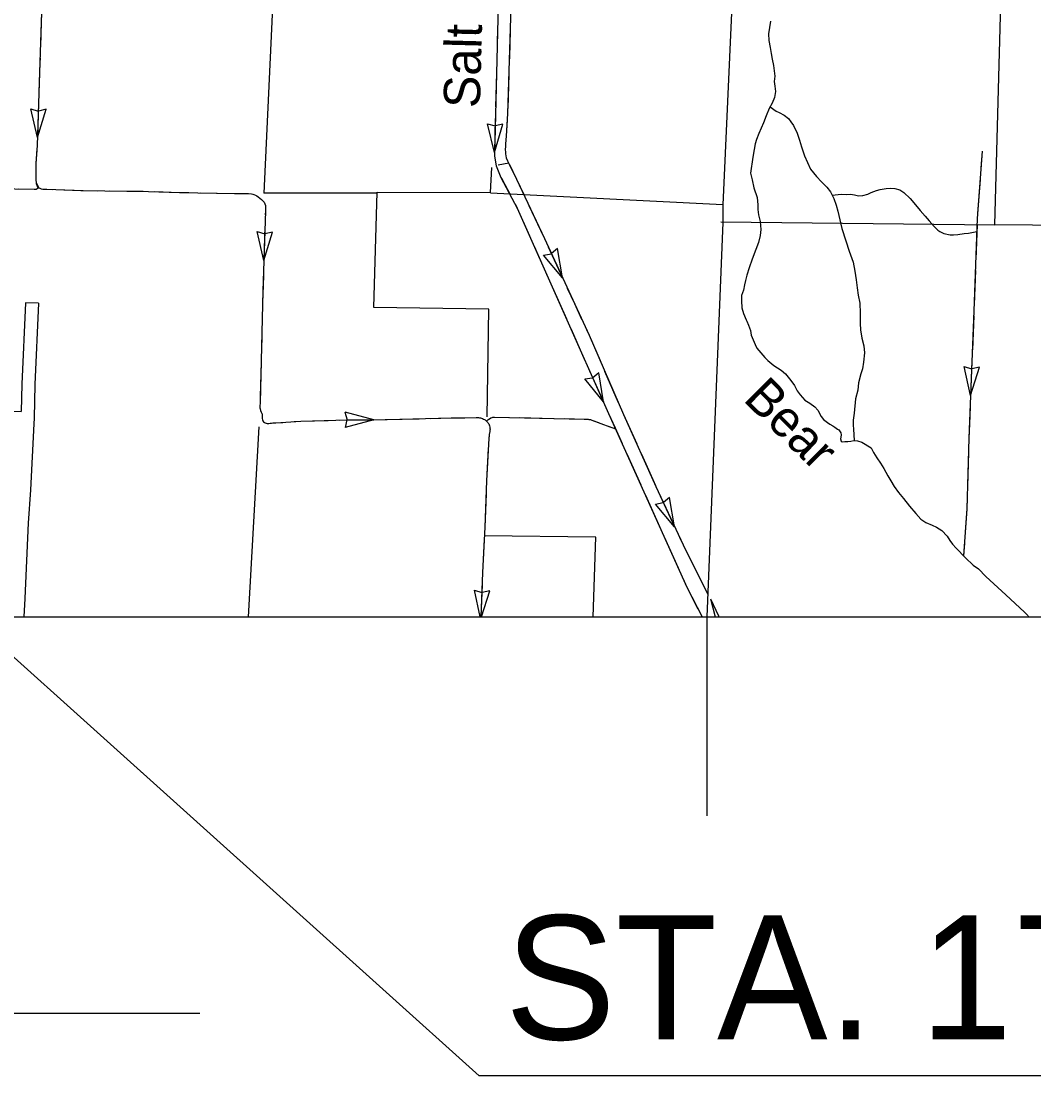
# Model space of a CAD drawing. Extents: x 1196286 to 1268366, y 2040822 to 2082115.
# Drawn here: x 1222892 to 1227299, y 2045968 to 2050559 of the extents above; entities that cross this region are included whole.
import ezdxf

# ---------------------------------------------------------------- set-up
doc = ezdxf.new("R2010")
doc.units = 0
for name, color, linetype in [('55', 7, 'Continuous'), ('60', 7, 'Continuous'), ('62', 7, 'Continuous'), ('63', 7, 'Continuous'), ('Level 70', 7, 'Continuous'), ('Level 72', 7, 'Continuous'), ('Level 8', 7, 'Continuous')]:
    doc.layers.add(name, color=color, linetype=linetype)

msp = doc.modelspace()

# ---------------------------------------------------------------- linework, layer by layer
at = {"layer": '55'}
msp.add_lwpolyline([(1226105.9, 2053795.1), (1226044.2, 2051971.2), (1226037.7, 2051807.6), (1226034.2, 2051719.9), (1225946, 2049758.8), (1225945.2, 2049681.6), (1225876.1, 2047966.3)], dxfattribs=at)
at = {"layer": '60'}
for points in [[(1223991.5, 2050744), (1223948.5, 2049810.4)], [(1224441.9, 2049810), (1223948.5, 2049810.4)], [(1225946, 2049758.8), (1224935.1, 2049809.8)], [(1225937.1, 2049684.5), (1227129.1, 2049672.5)], [(1223927.2, 2048792.6), (1223880.6, 2047966.3)]]:
    msp.add_lwpolyline(points, dxfattribs=at)
at = {"layer": '62'}
for points in [[(1226152.8, 2050559.2), (1226144.9, 2050503.4), (1226146.3, 2050474.4), (1226151.1, 2050444.3), (1226155.9, 2050417.9), (1226161.1, 2050393.1), (1226166.7, 2050365.2), (1226169.4, 2050343), (1226171.6, 2050319.7), (1226168.6, 2050296.4), (1226172.8, 2050276.1), (1226174.3, 2050252.4), (1226170.5, 2050226.1), (1226161.2, 2050202.2), (1226147.3, 2050178.4), (1226134.1, 2050147.1), (1226123.5, 2050116.4), (1226111.9, 2050093.3), (1226101.8, 2050069.1), (1226092.4, 2050043.3), (1226086.5, 2050025.3), (1226082, 2049999.5), (1226076.3, 2049966.5), (1226066.9, 2049896.8), (1226072.9, 2049868.2), (1226081.3, 2049833.1), (1226094.5, 2049790.4), (1226098.5, 2049759.2), (1226098.2, 2049738.2), (1226101.2, 2049715.9), (1226107.9, 2049686.2), (1226111.1, 2049651.2), (1226108.1, 2049625.7), (1226100.5, 2049594.6), (1226089.2, 2049565.1), (1226073.5, 2049522.9), (1226060.6, 2049484.4), (1226049.6, 2049452.7), (1226044.4, 2049429.4), (1226040.7, 2049411.5), (1226035.1, 2049388.3), (1226027.6, 2049364.3), (1226026.5, 2049341.4), (1226029, 2049310.2), (1226035.8, 2049285.7), (1226047.7, 2049258.1), (1226050.3, 2049253.5), (1226058.2, 2049236.1), (1226065.7, 2049212.4), (1226069.5, 2049191.3), (1226086.5, 2049150.8), (1226093.8, 2049135.7), (1226111, 2049114.7), (1226129.1, 2049094.9), (1226141.3, 2049082.3), (1226167.9, 2049060.5), (1226199.4, 2049039.4), (1226218.6, 2049023.3), (1226242.2, 2048994), (1226257.6, 2048972.7), (1226269.9, 2048949.2), (1226281.7, 2048932.1), (1226302.6, 2048908.5), (1226323.8, 2048896.2), (1226346, 2048880.4), (1226358.9, 2048865.6), (1226373.8, 2048837.9), (1226384.5, 2048825), (1226401.9, 2048812.3), (1226411.5, 2048804.6), (1226424.5, 2048797.3), (1226432.7, 2048791.9), (1226444.9, 2048783.1), (1226450.1, 2048780.4), (1226454.2, 2048776.2), (1226460, 2048767.1), (1226461, 2048758.4), (1226459.7, 2048747.5), (1226457.4, 2048740.8), (1226460.2, 2048730.3), (1226464.7, 2048727.6), (1226477.4, 2048728.9), (1226489.4, 2048729), (1226502.9, 2048731.1), (1226515.7, 2048733.9)], [(1226151.9, 2050186.2), (1226177.9, 2050167.4), (1226190.9, 2050160.8), (1226212.1, 2050148.9), (1226230.9, 2050135), (1226241.6, 2050121), (1226253.7, 2050105), (1226270, 2050071.3), (1226280.1, 2050041.1), (1226287.8, 2050011.7), (1226301.5, 2049972), (1226327.9, 2049914.1), (1226353.3, 2049881.8), (1226375.8, 2049859.7), (1226398.6, 2049835.7), (1226414.4, 2049815.5), (1226428.6, 2049786.3), (1226439.7, 2049757.6), (1226446.1, 2049732), (1226464, 2049655.8), (1226481.2, 2049603), (1226495.4, 2049557.3), (1226512.3, 2049509.7), (1226520.3, 2049470.5), (1226525.7, 2049432.1), (1226530.4, 2049397.8), (1226534.1, 2049365.5), (1226541.4, 2049331.9), (1226543.7, 2049287.9), (1226542.7, 2049243.2), (1226545.2, 2049215.4), (1226551, 2049179.3), (1226558.7, 2049144.9), (1226561.6, 2049114.5), (1226558.4, 2049074.3), (1226553.1, 2049045.5), (1226545.6, 2049023.4), (1226535.7, 2048984.9), (1226532.9, 2048952.6), (1226523.3, 2048914.5), (1226517.9, 2048852.2), (1226513.3, 2048822.6), (1226513.3, 2048800.4), (1226515, 2048783.5), (1226517.3, 2048733.8)], [(1226421.5, 2049801), (1226460.3, 2049805), (1226482.4, 2049803.9), (1226501.9, 2049805.1), (1226518.3, 2049802.2), (1226536.6, 2049798.2), (1226554.6, 2049799.8), (1226577.2, 2049805.4), (1226591.2, 2049812.7), (1226613.8, 2049821), (1226630.3, 2049826), (1226655.9, 2049830.1), (1226675, 2049832.1), (1226694.4, 2049830.3), (1226715.3, 2049824), (1226733.9, 2049812.8), (1226761.2, 2049786.4), (1226784.7, 2049759), (1226805, 2049735), (1226825.9, 2049710.3), (1226844, 2049689), (1226865.3, 2049664.2), (1226881.9, 2049648.9), (1226890.8, 2049642.4), (1226907.5, 2049634.3), (1226935.5, 2049628.2), (1226949, 2049628.7), (1226967.8, 2049629.9), (1226995.9, 2049634), (1227014.7, 2049636.3), (1227051.1, 2049643.6)], [(1226515.7, 2048733.9), (1226531.4, 2048732.5), (1226550.8, 2048726.2), (1226592, 2048702.3), (1226601.4, 2048681.8), (1226616, 2048658.3), (1226631.4, 2048634.8), (1226646.8, 2048611.6), (1226664.3, 2048579.8), (1226676.3, 2048557.5), (1226691.6, 2048533.6), (1226710.7, 2048507.7), (1226731.3, 2048481.5), (1226758.1, 2048447.6), (1226785.3, 2048415.3), (1226807.8, 2048391.6), (1226829.7, 2048376.6), (1226856.8, 2048364.6), (1226875.4, 2048356.4), (1226898.4, 2048342.1), (1226922, 2048317), (1226933.7, 2048298.4), (1226945.5, 2048282.4), (1226960.9, 2048264.5), (1227001.5, 2048222.9), (1227034.7, 2048191.6), (1227057.7, 2048175.1), (1227090.1, 2048141.9), (1227177.7, 2048061.7), (1227258.1, 2047986.8), (1227272.5, 2047971.9), (1227276.1, 2047966.3)], [(1225892, 2048044.5), (1225912.3, 2047966.3)], [(1225892, 2048044.5), (1225926.3, 2047970.7), (1225928.5, 2047966.3)]]:
    msp.add_lwpolyline(points, dxfattribs=at)
at = {"layer": '63'}
for p, q in [((1222963.6, 2050051.9), (1222934.4, 2050177.2)), ((1222934.4, 2050177.2), (1222967.2, 2050167.3)), ((1222963.6, 2050051.9), (1223001, 2050175)), ((1223001, 2050175), (1222967.6, 2050167.3)), ((1224952.2, 2049987.2), (1224921.9, 2050112.2)), ((1224921.9, 2050112.2), (1224954.8, 2050102.6)), ((1224952.2, 2049987.2), (1224988.5, 2050110.6)), ((1224988.5, 2050110.6), (1224955.2, 2050102.6)), ((1225014, 2049940.7), (1224968.7, 2049931.6)), ((1223948.8, 2049517.6), (1223919.4, 2049642.9)), ((1223919.4, 2049642.9), (1223952.2, 2049633)), ((1223948.8, 2049517.6), (1223986, 2049640.8)), ((1223986, 2049640.8), (1223952.6, 2049633)), ((1225166.1, 2049540.7), (1225199.9, 2049546.5)), ((1225248.4, 2049441.7), (1225166.1, 2049540.7)), ((1225226.7, 2049568.6), (1225200.3, 2049546.7)), ((1225248.4, 2049441.7), (1225226.7, 2049568.6)), ((1225406.4, 2049028.4), (1225379.8, 2049006.8)), ((1225426.5, 2048901.2), (1225406.4, 2049028.4)), ((1227024, 2048929.7), (1226995.7, 2049055.3)), ((1226995.7, 2049055.3), (1227028.4, 2049045.1)), ((1227024, 2048929.7), (1227062.3, 2049052.6)), ((1227062.3, 2049052.6), (1227028.9, 2049045.1)), ((1225345.5, 2049001.3), (1225379.4, 2049006.6)), ((1225426.5, 2048901.2), (1225345.5, 2049001.3)), ((1224301.4, 2048856.6), (1224311.3, 2048823.8)), ((1224426.8, 2048823.8), (1224302.4, 2048856.9)), ((1224426.8, 2048823.8), (1224302.5, 2048790.3)), ((1224303.5, 2048790), (1224311.3, 2048823.4)), ((1225713.6, 2048485.2), (1225687.3, 2048463.2)), ((1225735.9, 2048358.4), (1225713.6, 2048485.2)), ((1225653.2, 2048457), (1225686.9, 2048463)), ((1225735.9, 2048358.4), (1225653.2, 2048457)), ((1224890.5, 2047966.3), (1224864.8, 2048082.6)), ((1224864.8, 2048082.6), (1224897.5, 2048072.3)), ((1224895.5, 2047966.3), (1224931.4, 2048079.7)), ((1224931.4, 2048079.7), (1224897.9, 2048072.3))]:
    msp.add_line(p, q, dxfattribs=at)
for points in [[(1224978.1, 2051051.1), (1224951.7, 2049970.3), (1224960.1, 2049929.6), (1224980.1, 2049878.3), (1225051, 2049744.6), (1225448.7, 2048851.4), (1225789, 2048095.3), (1225855.5, 2047966.3)], [(1225029.5, 2050806.5), (1225009.5, 2050156.7), (1225003, 2050058.6), (1225000.4, 2050024.1), (1224999.6, 2050013.8), (1224999, 2049998.3), (1224999.4, 2049989.8), (1225000, 2049980.7), (1225001.2, 2049972.9), (1225003.5, 2049963.7), (1225008.7, 2049950.8), (1225016.1, 2049936.7), (1225048.3, 2049870.6), (1225169.4, 2049613.3), (1225363.6, 2049191.3), (1225513.1, 2048847.3), (1225654.1, 2048534), (1225772.6, 2048279.5), (1225880, 2048063.8)], [(1222983.9, 2050670.3), (1222979.9, 2050553.7), (1222974, 2050379.2), (1222968.5, 2050200), (1222962.5, 2050017.5), (1222957, 2049938.5), (1222956.5, 2049898.9), (1222956.6, 2049878), (1222956.8, 2049865.9), (1222957.3, 2049856.8), (1222957.8, 2049852.1), (1222958.8, 2049847.3), (1222961.1, 2049842.2), (1222963, 2049838.7), (1222964.3, 2049837), (1222966, 2049835.3), (1222967.3, 2049834.3)], [(1222981.4, 2050596.1), (1222979.9, 2050553.7), (1222976.3, 2050447.7)], [(1224965.4, 2050531.5), (1224961.8, 2050383)], [(1225020.8, 2050524.7), (1225018.5, 2050450.4)], [(1225018.5, 2050450.4), (1225016.2, 2050376.2)], [(1222974.6, 2050398.2), (1222974, 2050379.2), (1222970, 2050249.8)], [(1224960.6, 2050333.6), (1224957, 2050185.1)], [(1225014.7, 2050326.8), (1225010.1, 2050178.3)], [(1222968.5, 2050200.3), (1222968.5, 2050200), (1222963.6, 2050051.9)], [(1224955.8, 2050135.6), (1224952.2, 2049987.2)], [(1225007.6, 2050128.9), (1225003, 2050058.6), (1225000.4, 2050024.1), (1224999.6, 2050013.8), (1224999, 2049998.3), (1224999.4, 2049989.8), (1225000, 2049980.7), (1225000, 2049980.7)], [(1222961.4, 2050002.4), (1222957, 2049938.5), (1222956.9, 2049928.3)], [(1227074.5, 2049992.7), (1227053.1, 2049700), (1227038.7, 2049297.5), (1227016.6, 2048743.7), (1227007.4, 2048436.2), (1226993, 2048231.7)], [(1227074.5, 2049992.7), (1227053.1, 2049700), (1227038.7, 2049297.5), (1227016.6, 2048743.7), (1227007.4, 2048436.2), (1226993, 2048231.7)], [(1227074.5, 2049992.7), (1227069.1, 2049918.6)], [(1222956.9, 2049928.3), (1222956.5, 2049898.9), (1222956.6, 2049878), (1222956.8, 2049865.9), (1222957.3, 2049856.8), (1222969.2, 2049833)], [(1224958.3, 2049938.3), (1224960.1, 2049929.6), (1224980.1, 2049878.3), (1224984.9, 2049869.2)], [(1225017.1, 2049934.6), (1225048.3, 2049870.6), (1225081.2, 2049800.7)], [(1224984.9, 2049869.2), (1225019.7, 2049803.6)], [(1227065.5, 2049869.2), (1227054.7, 2049721.1)], [(1221967.6, 2049848.8), (1222178.4, 2049845.5), (1222865, 2049829.2), (1222949.7, 2049827), (1222955.3, 2049827.3), (1222958.6, 2049828), (1222962, 2049829.8), (1222967.3, 2049834.3)], [(1222883.1, 2049828.7), (1222949.7, 2049827), (1222955.3, 2049827.3), (1222958.6, 2049828), (1222962, 2049829.8), (1222967.3, 2049834.3), (1222969.2, 2049833), (1222973.8, 2049831.2), (1222980.2, 2049829.1), (1222987.2, 2049827.8), (1222992.9, 2049827.3), (1222999.2, 2049826.7), (1223003.9, 2049826.7), (1223028.1, 2049825.9)], [(1222967.3, 2049834.3), (1222969.2, 2049833), (1222973.8, 2049831.2), (1222980.2, 2049829.1), (1222987.2, 2049827.8), (1222992.9, 2049827.3), (1222999.2, 2049826.7), (1223003.9, 2049826.7), (1223162.3, 2049821.7), (1223446.9, 2049817.8), (1223581.8, 2049812.9), (1223822.7, 2049808.6), (1223881.1, 2049807.8), (1223894.8, 2049806.5), (1223901.1, 2049805.4), (1223905.6, 2049804), (1223911.7, 2049801.2), (1223917.5, 2049798.3), (1223924.5, 2049793.8), (1223931.1, 2049788.7), (1223938.5, 2049782), (1223943.9, 2049776.8), (1223949.3, 2049770.2), (1223953, 2049763.1), (1223955.2, 2049756.6), (1223956, 2049751.3), (1223956.1, 2049745.7), (1223955.5, 2049732.2), (1223944.8, 2049385.1), (1223932, 2048898.4), (1223931.3, 2048880.9), (1223931.2, 2048876.3), (1223932.1, 2048870.8), (1223934.5, 2048863.6), (1223937.1, 2048857.4), (1223939.9, 2048851.6), (1223940.7, 2048849), (1223941, 2048845.7), (1223941, 2048841.2), (1223941, 2048837), (1223941.2, 2048829.6), (1223942.1, 2048823.7), (1223944, 2048818.9), (1223947.2, 2048814.9), (1223951.1, 2048812), (1223954.5, 2048810), (1223958.9, 2048808.7), (1223963.1, 2048808), (1223966.3, 2048807.9), (1223970.9, 2048808.1), (1223976, 2048808.6), (1223982.5, 2048809.2), (1223987.8, 2048809.7), (1224001, 2048810.7), (1224109.4, 2048817.4), (1224312.3, 2048823.6), (1224423.3, 2048823.8), (1224485.9, 2048824.5), (1224763.7, 2048831.8), (1224876.5, 2048833.3), (1224883.1, 2048832.9), (1224887.4, 2048832.5), (1224890.9, 2048831.8), (1224895.2, 2048830.8), (1224900.5, 2048828.9), (1224904.8, 2048827), (1224908.1, 2048825.4), (1224911, 2048823.5), (1224914.1, 2048821), (1224917.6, 2048817.7)], [(1223077.6, 2049824.4), (1223151.8, 2049822)], [(1223151.8, 2049822), (1223162.3, 2049821.7), (1223226, 2049820.8)], [(1223275.5, 2049820.2), (1223424, 2049818.1)], [(1223473.5, 2049816.8), (1223581.8, 2049812.9), (1223621.9, 2049812.2)], [(1223671.4, 2049811.3), (1223819.9, 2049808.6)], [(1223869.4, 2049807.9), (1223881.1, 2049807.8), (1223894.8, 2049806.5), (1223901.1, 2049805.4), (1223905.6, 2049804), (1223911.7, 2049801.2), (1223917.5, 2049798.3), (1223924.5, 2049793.8), (1223931.1, 2049788.7), (1223938.5, 2049782), (1223943.9, 2049776.8), (1223949.3, 2049770.2), (1223953, 2049763.1), (1223955.2, 2049756.6), (1223956, 2049751.3), (1223956.1, 2049745.7), (1223955.5, 2049732.2), (1223955, 2049715.5)], [(1225042.9, 2049759.9), (1225051, 2049744.6), (1225104.4, 2049624.8)], [(1225102.3, 2049755.9), (1225165.5, 2049621.6)], [(1227052.1, 2049671.7), (1227046.8, 2049523.3)], [(1223953.4, 2049666), (1223948.8, 2049517.6)], [(1225124.5, 2049579.6), (1225184.9, 2049443.9)], [(1225186.3, 2049576.6), (1225248.4, 2049441.7)], [(1223947.3, 2049468.1), (1223945, 2049393.9)], [(1227045, 2049473.8), (1227039.7, 2049325.4)], [(1223945, 2049393.9), (1223944.8, 2049385.1), (1223943, 2049319.7)], [(1225205.1, 2049398.7), (1225265.4, 2049263)], [(1225269.1, 2049396.8), (1225300.1, 2049329.3)], [(1225300.1, 2049329.3), (1225331.2, 2049261.9)], [(1223941.7, 2049270.2), (1223937.9, 2049121.7)], [(1227037.8, 2049276), (1227031.9, 2049127.6)], [(1225285.6, 2049217.8), (1225346, 2049082.1)], [(1225351.9, 2049216.9), (1225363.6, 2049191.3), (1225411.6, 2049081)], [(1223936.6, 2049072.3), (1223932.7, 2048923.8)], [(1227029.9, 2049078.1), (1227024, 2048929.7)], [(1225366.1, 2049036.9), (1225426.5, 2048901.2)], [(1225431.3, 2049035.6), (1225490.5, 2048899.4)], [(1223931.6, 2048874.4), (1223932.1, 2048870.8), (1223934.5, 2048863.6), (1223937.1, 2048857.4), (1223939.9, 2048851.6), (1223940.7, 2048849), (1223941, 2048845.7), (1223941, 2048841.2), (1223941, 2048837), (1223941.2, 2048829.6), (1223942.1, 2048823.7), (1223944, 2048818.9), (1223947.2, 2048814.9), (1223951.1, 2048812), (1223954.5, 2048810), (1223958.9, 2048808.7), (1223963.1, 2048808), (1223966.3, 2048807.9), (1223970.9, 2048808.1), (1223976, 2048808.6), (1223982.5, 2048809.2), (1223987.8, 2048809.7), (1224001, 2048810.7), (1224031, 2048812.5)], [(1225446.6, 2048856), (1225448.7, 2048851.4), (1225477.1, 2048788.3)], [(1225510.3, 2048854), (1225513.1, 2048847.3), (1225571.1, 2048718.5)], [(1227022.1, 2048880.3), (1227019.1, 2048806.1)], [(1224080.4, 2048815.6), (1224109.4, 2048817.4), (1224228.8, 2048821)], [(1224278.3, 2048822.6), (1224312.3, 2048823.6), (1224423.3, 2048823.8), (1224426.8, 2048823.8)], [(1224476.3, 2048824.4), (1224485.9, 2048824.5), (1224550.5, 2048826.2)], [(1224550.5, 2048826.2), (1224624.7, 2048828.1)], [(1224674.2, 2048829.4), (1224763.7, 2048831.8), (1224822.7, 2048832.6)], [(1224872.2, 2048833.3), (1224876.5, 2048833.3), (1224883.1, 2048832.9), (1224887.4, 2048832.5), (1224890.9, 2048831.8), (1224895.2, 2048830.8), (1224900.5, 2048828.9), (1224904.8, 2048827), (1224908.1, 2048825.4), (1224911, 2048823.5), (1224914.1, 2048821), (1224917.6, 2048817.7), (1224923.7, 2048823), (1224927.5, 2048826), (1224930.5, 2048828), (1224936.2, 2048831.5), (1224942.2, 2048834.3), (1224945.3, 2048835.2), (1224947.7, 2048835.6), (1224952.2, 2048835.6), (1225011.1, 2048834.3)], [(1224917.6, 2048817.7), (1224920.5, 2048814.7), (1224922.8, 2048811.9), (1224924.9, 2048808.9), (1224927.1, 2048805.4), (1224929, 2048801.4), (1224930.5, 2048797.2), (1224931.8, 2048792.2), (1224932.5, 2048787.6), (1224932.8, 2048783.1), (1224932.6, 2048779), (1224931.7, 2048772.6), (1224929, 2048758.9), (1224928.4, 2048753.8), (1224927.4, 2048743.8), (1224918, 2048557.8), (1224909.7, 2048356.9), (1224900.5, 2048159), (1224892.9, 2047966.3)], [(1224917.6, 2048817.7), (1224923.7, 2048823), (1224927.5, 2048826), (1224930.5, 2048828), (1224936.2, 2048831.5), (1224942.2, 2048834.3), (1224945.3, 2048835.2), (1224947.7, 2048835.6), (1224952.2, 2048835.6), (1225342.1, 2048826.9), (1225351.7, 2048826.4), (1225359.6, 2048825.8), (1225362.1, 2048825.6), (1225366.5, 2048824.9), (1225369.4, 2048824.2), (1225375.7, 2048822.3), (1225453.4, 2048793.7)], [(1224917.6, 2048817.7), (1224920.5, 2048814.7), (1224922.8, 2048811.9), (1224924.9, 2048808.9), (1224927.1, 2048805.4), (1224929, 2048801.4), (1224930.5, 2048797.2), (1224931.8, 2048792.2), (1224932.5, 2048787.6), (1224932.8, 2048783.1), (1224932.6, 2048779), (1224931.7, 2048772.6), (1224929, 2048758.9), (1224928.4, 2048753.8), (1224927.8, 2048748)], [(1225060.6, 2048833.2), (1225209.1, 2048829.8)], [(1225258.6, 2048828.7), (1225342.1, 2048826.9), (1225351.7, 2048826.4), (1225359.6, 2048825.8), (1225362.1, 2048825.6), (1225366.5, 2048824.9), (1225369.4, 2048824.2), (1225375.7, 2048822.3), (1225404.7, 2048811.6)], [(1225451.1, 2048794.5), (1225478.9, 2048784.3)], [(1227019.1, 2048806.1), (1227016.6, 2048743.7), (1227016.3, 2048731.9)], [(1225477.1, 2048788.3), (1225507.6, 2048720.6)], [(1224925.1, 2048698.6), (1224918, 2048557.8), (1224917.7, 2048550.3)], [(1225527.9, 2048675.5), (1225588.8, 2048540)], [(1225591.4, 2048673.4), (1225652.3, 2048537.9)], [(1227014.8, 2048682.4), (1227010.3, 2048534)], [(1224915.6, 2048500.8), (1224909.7, 2048356.9), (1224909.5, 2048352.4)], [(1225609.1, 2048494.9), (1225670.1, 2048359.5)], [(1225673.1, 2048493), (1225735.9, 2048358.4)], [(1227008.8, 2048484.5), (1227007.4, 2048436.2), (1227000.3, 2048336.3)], [(1224907.2, 2048303), (1224900.5, 2048159), (1224900.4, 2048154.7)], [(1225690.4, 2048314.3), (1225751.4, 2048178.9)], [(1225756.8, 2048313.5), (1225772.6, 2048279.5), (1225789, 2048246.7)], [(1225789, 2048246.7), (1225822.1, 2048180.2)], [(1226996.9, 2048286.9), (1226993, 2048231.7)], [(1225771.7, 2048133.8), (1225789, 2048095.3), (1225837.7, 2048000.8)], [(1225844.2, 2048135.9), (1225880, 2048063.8)], [(1224898.4, 2048105.2), (1224892.9, 2047966.3)]]:
    msp.add_lwpolyline(points, dxfattribs=at)
at = {"layer": 'Level 70'}
for points in [[(1231056.2, 2048057.5), (1230559.8, 2048076.9), (1229033.8, 2048122.5), (1229048.7, 2048648.2), (1228562.2, 2048668.5), (1228540.1, 2048166.7), (1227567.9, 2048203.2), (1227620.1, 2049667.6), (1227129.1, 2049672.5), (1227157.2, 2050690.5), (1227491.2, 2050685.6), (1227647.6, 2050670.1), (1227657.4, 2051038.4)], [(1224920.1, 2048836.3), (1224928.3, 2049305.6), (1224427.2, 2049312.8), (1224442, 2049814.3), (1224935.2, 2049812.7), (1224940.2, 2049922.1)], [(1225381.9, 2047966.3), (1225393.9, 2048312.4), (1224907.9, 2048318.1)]]:
    msp.add_lwpolyline(points, dxfattribs=at)
at = {"layer": 'Level 72'}
for points in [[(1222967.8, 2049330.7), (1222911.6, 2049333.3), (1222895.2, 2048978.5), (1222892.9, 2048859.4)], [(1222967.8, 2049330.7), (1222951.5, 2048976.6), (1222948.6, 2048830.1)], [(1221967.2, 2048884.6), (1221990.5, 2048883.6), (1222094, 2048880.6), (1222374, 2048874.3), (1222832.2, 2048860.8), (1222892.9, 2048859.4)], [(1222948.6, 2048830.1), (1222948.1, 2048805.6), (1222933.6, 2048518.9), (1222922.3, 2048373.8)], [(1222922.3, 2048374.7), (1222908.2, 2048045.5), (1222904.4, 2047966.3)]]:
    msp.add_lwpolyline(points, dxfattribs=at)
at = {"layer": 'Level 8'}
for p, q in [((1218352.6, 2051843.3), (1224885.6, 2045968.1)), ((1225876.1, 2047966.3), (1225876.1, 2047099.8)), ((1223669.6, 2046239.2), (1215694.3, 2046239.2)), ((1231068, 2045968.1), (1224885.6, 2045968.1))]:
    msp.add_line(p, q, dxfattribs=at)
msp.add_lwpolyline([(1241590.6, 2065596.8), (1214332.8, 2065596.8), (1214332.8, 2047966.3), (1241590.6, 2047966.3)], close=True, dxfattribs=at)

# ---------------------------------------------------------------- texts
at = {"layer": '60'}
msp.add_text('STA. 176+40.00', height=540, dxfattribs=at).set_placement((1224997.7, 2046126.6))
at = {"layer": '62'}
msp.add_text('Bear', height=158.4, rotation=315.2743, dxfattribs=at).set_placement((1226030.3, 2048909.4))
at = {"layer": '63'}
msp.add_text('Salt', height=158.4, rotation=88.5497, dxfattribs=at).set_placement((1224888.6, 2050179))

doc.saveas('drawing.dxf')
